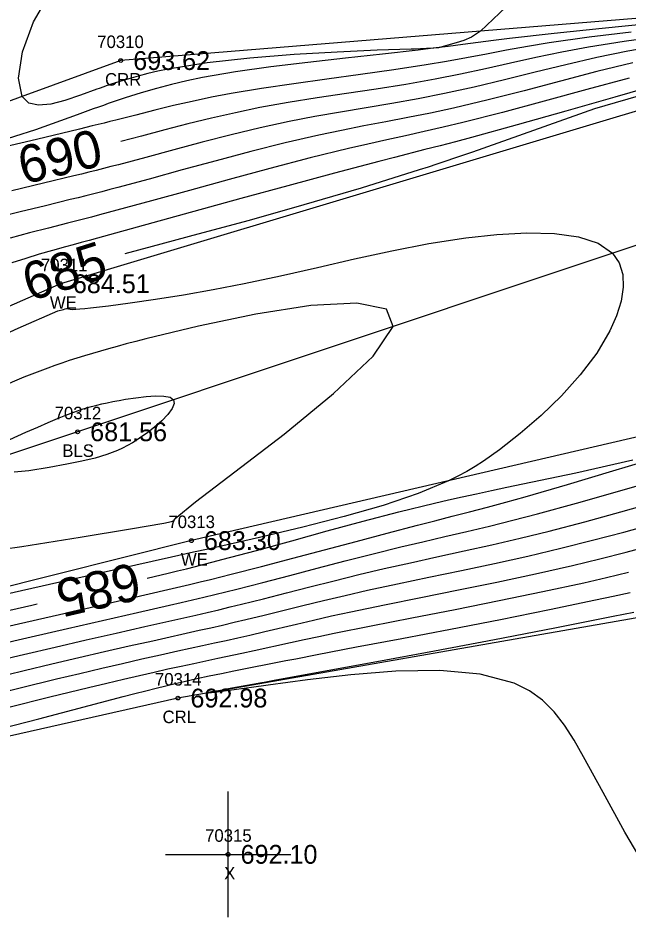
# Model space of a CAD drawing. Extents: x 1376587 to 1378239, y 1000335 to 1003031.
# Drawn here: x 1377106.6 to 1377155.3, y 1001513.1 to 1001584.8 of the extents above; entities that cross this region are included whole.
import ezdxf

# ---------------------------------------------------------------- set-up
doc = ezdxf.new("R2010")
doc.units = 0
for name, color, linetype in [('RD_DTM_BkLn1', 7, 'Continuous'), ('RD_DTM_BkLn_txCode', 7, 'Continuous'), ('RD_DTM_Major1', 7, 'Continuous'), ('RD_DTM_Major1_Lbl', 7, 'Continuous'), ('RD_DTM_Minor1', 7, 'Continuous'), ('RD_EX_H2O', 7, 'Continuous'), ('RD_EX_H2O_txCode', 7, 'Continuous'), ('RD_EX_Misc', 7, 'Continuous'), ('RD_EX_Misc_txCode', 7, 'Continuous'), ('RD_EX_TX_H2O_ELEV', 7, 'Continuous'), ('RD_EX_TX_Misc_ELEV', 7, 'Continuous'), ('RD_SMD_Locator', 7, 'Continuous')]:
    doc.layers.add(name, color=color, linetype=linetype)

msp = doc.modelspace()

# ---------------------------------------------------------------- linework, layer by layer
at = {"layer": 'RD_DTM_BkLn1'}
msp.add_lwpolyline([(1377322.969, 1001642.525), (1377293.605, 1001607.098), (1377249.432, 1001558.553), (1377170.427, 1001571.461), (1377111.377, 1001551.766), (1377054.733, 1001532.92), (1377033.73, 1001527.24), (1376971.435, 1001536.185), (1376926.988, 1001576.278)], dxfattribs=at)
at = {"layer": 'RD_DTM_Major1'}
for points in [[(1377157.881, 1001583.305), (1377154.99, 1001582.908), (1377152.156, 1001582.449), (1377150.02, 1001582.045), (1377147.949, 1001581.613), (1377145.922, 1001581.168), (1377143.919, 1001580.723), (1377141.921, 1001580.293), (1377139.909, 1001579.891), (1377137.566, 1001579.477), (1377135.2, 1001579.102), (1377132.831, 1001578.747), (1377130.482, 1001578.395), (1377128.174, 1001578.027), (1377125.928, 1001577.626), (1377123.968, 1001577.224), (1377122.059, 1001576.788), (1377120.184, 1001576.327), (1377118.325, 1001575.848), (1377116.466, 1001575.36), (1377114.833, 1001574.934)], [(1377156.946, 1001578.77), (1377152.642, 1001577.526), (1377147.765, 1001575.8), (1377142.89, 1001574.08), (1377142.173, 1001573.835), (1377141.461, 1001573.593), (1377140.752, 1001573.355), (1377140.046, 1001573.12), (1377139.341, 1001572.888), (1377138.635, 1001572.659), (1377134.009, 1001571.213), (1377129.443, 1001569.867), (1377125.058, 1001568.633), (1377120.977, 1001567.521), (1377117.32, 1001566.544), (1377115.147, 1001565.962)], [(1377116.914, 1001540.081), (1377118.593, 1001540.484), (1377119.334, 1001540.666), (1377120.061, 1001540.847), (1377120.776, 1001541.027), (1377121.485, 1001541.207), (1377122.19, 1001541.388), (1377122.896, 1001541.572), (1377125.66, 1001542.311), (1377128.466, 1001543.079), (1377131.302, 1001543.858), (1377134.154, 1001544.629), (1377137.01, 1001545.373), (1377139.858, 1001546.072), (1377140.964, 1001546.329), (1377142.08, 1001546.58), (1377143.22, 1001546.83), (1377144.396, 1001547.083), (1377145.623, 1001547.343), (1377146.913, 1001547.614), (1377151.134, 1001548.507), (1377155.692, 1001549.527)], [(1377103.735, 1001530.596), (1377106.791, 1001531.352), (1377109.684, 1001532.056), (1377111.544, 1001532.5), (1377113.297, 1001532.912), (1377114.95, 1001533.295), (1377116.51, 1001533.649), (1377117.985, 1001533.98), (1377119.381, 1001534.288), (1377121.341, 1001534.716), (1377122.288, 1001534.923), (1377123.229, 1001535.13), (1377124.172, 1001535.341), (1377125.13, 1001535.559), (1377126.312, 1001535.835), (1377128.833, 1001536.43), (1377130.197, 1001536.747), (1377131.645, 1001537.075), (1377133.192, 1001537.413), (1377135.87, 1001537.972), (1377138.755, 1001538.554), (1377141.772, 1001539.158), (1377144.847, 1001539.785), (1377147.907, 1001540.435), (1377150.878, 1001541.106), (1377153.057, 1001541.635), (1377155.168, 1001542.172), (1377157.238, 1001542.714)], [(1377077.245, 1001530.968), (1377081.358, 1001531.909), (1377085.388, 1001532.835), (1377089.149, 1001533.702), (1377090.474, 1001534.009), (1377091.751, 1001534.304), (1377093.001, 1001534.594), (1377094.242, 1001534.88), (1377095.493, 1001535.168), (1377096.773, 1001535.461), (1377100.254, 1001536.252), (1377103.943, 1001537.085), (1377107.732, 1001537.944), (1377108.148, 1001538.039)]]:
    msp.add_lwpolyline(points, dxfattribs=at)
at = {"layer": 'RD_DTM_Minor1'}
for points in [[(1377146.071, 1001586.122), (1377143.533, 1001583.723), (1377142.824, 1001583.234), (1377142.198, 1001582.984), (1377141.581, 1001582.805), (1377140.179, 1001582.401), (1377139.448, 1001582.342), (1377139.223, 1001582.332), (1377138.991, 1001582.323), (1377138.753, 1001582.314), (1377138.256, 1001582.299), (1377137.996, 1001582.291), (1377135.281, 1001582.201), (1377132.102, 1001582.062), (1377128.653, 1001581.858), (1377125.125, 1001581.573), (1377121.714, 1001581.19), (1377118.611, 1001580.694), (1377117.772, 1001580.522), (1377116.972, 1001580.338), (1377116.205, 1001580.142), (1377115.465, 1001579.936), (1377114.745, 1001579.718), (1377114.041, 1001579.489), (1377113.85, 1001579.424), (1377113.659, 1001579.358), (1377113.468, 1001579.291), (1377113.089, 1001579.157), (1377112.9, 1001579.089), (1377111.598, 1001578.617), (1377110.36, 1001578.2), (1377109.231, 1001577.909), (1377108.255, 1001577.817), (1377107.478, 1001577.995), (1377106.944, 1001578.514), (1377106.664, 1001579.987), (1377106.982, 1001582.073), (1377107.854, 1001584.463), (1377109.236, 1001586.852)], [(1377157.167, 1001584.344), (1377153.234, 1001583.948), (1377149.405, 1001583.546), (1377145.85, 1001583.14), (1377144.566, 1001582.98), (1377143.332, 1001582.822), (1377142.132, 1001582.665), (1377140.949, 1001582.509), (1377139.764, 1001582.357), (1377138.561, 1001582.208), (1377135.706, 1001581.88), (1377132.744, 1001581.559), (1377129.751, 1001581.229), (1377126.803, 1001580.873), (1377123.977, 1001580.478), (1377121.348, 1001580.027), (1377120.093, 1001579.768), (1377118.879, 1001579.483), (1377117.676, 1001579.165), (1377116.452, 1001578.807), (1377115.178, 1001578.403), (1377113.821, 1001577.945), (1377113.429, 1001577.809), (1377113.028, 1001577.668), (1377112.619, 1001577.523), (1377112.199, 1001577.373), (1377111.769, 1001577.219), (1377111.329, 1001577.06), (1377108.007, 1001575.865), (1377104.642, 1001574.792)], [(1377155.556, 1001583.646), (1377152.2, 1001583.235), (1377149.019, 1001582.782), (1377147.277, 1001582.497), (1377145.612, 1001582.202), (1377143.997, 1001581.902), (1377142.406, 1001581.603), (1377140.81, 1001581.31), (1377139.182, 1001581.029), (1377136.607, 1001580.63), (1377133.95, 1001580.257), (1377131.269, 1001579.897), (1377128.62, 1001579.536), (1377126.059, 1001579.161), (1377123.642, 1001578.759), (1377122.05, 1001578.453), (1377120.524, 1001578.128), (1377119.03, 1001577.783), (1377117.536, 1001577.418), (1377116.008, 1001577.033), (1377114.412, 1001576.63), (1377113.958, 1001576.515), (1377113.494, 1001576.399), (1377113.021, 1001576.282), (1377112.537, 1001576.162), (1377112.041, 1001576.04), (1377111.533, 1001575.915), (1377108.084, 1001575.087), (1377104.31, 1001574.194)], [(1377157.754, 1001582.569), (1377155.301, 1001582.131), (1377152.824, 1001581.614), (1377150.351, 1001581.044), (1377147.89, 1001580.445), (1377145.448, 1001579.845), (1377143.031, 1001579.269), (1377140.646, 1001578.745), (1377138.542, 1001578.333), (1377136.462, 1001577.964), (1377134.401, 1001577.618), (1377132.352, 1001577.275), (1377130.308, 1001576.917), (1377128.264, 1001576.523), (1377125.941, 1001576.017), (1377123.621, 1001575.459), (1377121.317, 1001574.867), (1377119.042, 1001574.26), (1377116.807, 1001573.655), (1377114.626, 1001573.073), (1377114.036, 1001572.919), (1377113.45, 1001572.767), (1377112.863, 1001572.617), (1377112.275, 1001572.468), (1377111.682, 1001572.32), (1377111.082, 1001572.173), (1377108.655, 1001571.59), (1377106.124, 1001570.992)], [(1377155.683, 1001581.205), (1377152.826, 1001580.498), (1377149.916, 1001579.742), (1377147.005, 1001578.978), (1377144.145, 1001578.248), (1377141.388, 1001577.592), (1377139.536, 1001577.194), (1377137.737, 1001576.835), (1377135.97, 1001576.497), (1377134.21, 1001576.163), (1377132.436, 1001575.815), (1377130.625, 1001575.435), (1377127.946, 1001574.816), (1377125.198, 1001574.125), (1377122.435, 1001573.394), (1377119.71, 1001572.653), (1377117.078, 1001571.931), (1377114.59, 1001571.259), (1377113.938, 1001571.087), (1377113.297, 1001570.92), (1377112.665, 1001570.757), (1377112.039, 1001570.597), (1377111.415, 1001570.441), (1377110.789, 1001570.285), (1377108.809, 1001569.803), (1377106.788, 1001569.313), (1377104.731, 1001568.797)], [(1377155.386, 1001579.987), (1377152.026, 1001579.073), (1377148.623, 1001578.138), (1377145.287, 1001577.238), (1377142.129, 1001576.433), (1377140.549, 1001576.057), (1377139.026, 1001575.711), (1377137.534, 1001575.382), (1377136.048, 1001575.056), (1377134.542, 1001574.721), (1377132.99, 1001574.363), (1377129.931, 1001573.611), (1377126.727, 1001572.776), (1377123.481, 1001571.899), (1377120.295, 1001571.023), (1377117.271, 1001570.188), (1377114.51, 1001569.435), (1377113.81, 1001569.248), (1377113.133, 1001569.069), (1377112.475, 1001568.896), (1377111.832, 1001568.729), (1377111.2, 1001568.566), (1377110.573, 1001568.407), (1377109.059, 1001568.022), (1377107.538, 1001567.629), (1377105.992, 1001567.212)], [(1377158.039, 1001579.541), (1377154.253, 1001578.471), (1377150.339, 1001577.349), (1377146.465, 1001576.249), (1377142.8, 1001575.24), (1377141.536, 1001574.905), (1377140.307, 1001574.586), (1377139.098, 1001574.276), (1377136.673, 1001573.658), (1377135.426, 1001573.337), (1377131.879, 1001572.404), (1377128.157, 1001571.399), (1377124.403, 1001570.37), (1377117.377, 1001568.426), (1377114.394, 1001567.606), (1377112.965, 1001567.217), (1377112.298, 1001567.036), (1377111.655, 1001566.862), (1377111.031, 1001566.692), (1377110.42, 1001566.525), (1377109.363, 1001566.231), (1377108.307, 1001565.927), (1377107.23, 1001565.601), (1377106.112, 1001565.241)], [(1377110.238, 1001561.521), (1377110.391, 1001561.571), (1377110.491, 1001561.596), (1377110.554, 1001561.602), (1377110.593, 1001561.595), (1377110.652, 1001561.564), (1377110.771, 1001561.541), (1377110.963, 1001561.536), (1377111.226, 1001561.548), (1377111.556, 1001561.573), (1377111.949, 1001561.611), (1377112.401, 1001561.659), (1377113.829, 1001561.827), (1377115.579, 1001562.054), (1377117.594, 1001562.343), (1377119.82, 1001562.694), (1377122.2, 1001563.109), (1377124.678, 1001563.588), (1377127.578, 1001564.211), (1377130.518, 1001564.882), (1377133.481, 1001565.559), (1377136.451, 1001566.204), (1377139.412, 1001566.776), (1377142.347, 1001567.236), (1377144.847, 1001567.513), (1377147.236, 1001567.641), (1377149.433, 1001567.588), (1377151.359, 1001567.321), (1377152.934, 1001566.806), (1377154.079, 1001566.008), (1377154.606, 1001565.235), (1377154.881, 1001564.321), (1377154.923, 1001563.294), (1377154.754, 1001562.183), (1377154.394, 1001561.016), (1377153.863, 1001559.821), (1377152.809, 1001558.052), (1377151.496, 1001556.315), (1377149.994, 1001554.643), (1377148.374, 1001553.068), (1377146.706, 1001551.622), (1377145.06, 1001550.338), (1377144.408, 1001549.867), (1377143.76, 1001549.425), (1377143.105, 1001549.007), (1377142.433, 1001548.61), (1377141.731, 1001548.23), (1377140.988, 1001547.863), (1377138.552, 1001546.847), (1377135.753, 1001545.898), (1377132.662, 1001545.004), (1377129.353, 1001544.154), (1377125.899, 1001543.337), (1377122.37, 1001542.542), (1377121.791, 1001542.413), (1377120.63, 1001542.155), (1377118.867, 1001541.765), (1377114.47, 1001540.786), (1377109.96, 1001539.775), (1377105.476, 1001538.762)], [(1377118.868, 1001544.604), (1377118.96, 1001544.637), (1377119.013, 1001544.666), (1377119.045, 1001544.697), (1377119.104, 1001544.789), (1377119.161, 1001544.862), (1377120.771, 1001546.184), (1377123.933, 1001548.569), (1377127.87, 1001551.588), (1377131.805, 1001554.812), (1377134.96, 1001557.814), (1377136.557, 1001560.164), (1377136.021, 1001561.55), (1377133.648, 1001562.039), (1377129.989, 1001561.838), (1377125.596, 1001561.157), (1377121.021, 1001560.202), (1377116.813, 1001559.182), (1377116.015, 1001558.976), (1377115.257, 1001558.775), (1377114.534, 1001558.58), (1377113.846, 1001558.389), (1377113.189, 1001558.202), (1377112.561, 1001558.019), (1377111.919, 1001557.827), (1377111.302, 1001557.636), (1377110.705, 1001557.445), (1377110.123, 1001557.252), (1377109.552, 1001557.056), (1377108.986, 1001556.855), (1377107.07, 1001556.121), (1377105.147, 1001555.308)], [(1377078.121, 1001546.544), (1377079.235, 1001547.086), (1377080.408, 1001547.672), (1377081.775, 1001548.356), (1377083.468, 1001549.197), (1377085.621, 1001550.252), (1377088.367, 1001551.576), (1377091.634, 1001553.138), (1377096.482, 1001555.399), (1377101.84, 1001557.863), (1377106.633, 1001560.036), (1377109.79, 1001561.42), (1377110.238, 1001561.521)], [(1377105.971, 1001551.161), (1377107.251, 1001551.732), (1377108.189, 1001552.146), (1377109.02, 1001552.508), (1377109.764, 1001552.824), (1377110.44, 1001553.097), (1377111.069, 1001553.335), (1377111.67, 1001553.541), (1377112.077, 1001553.668), (1377112.484, 1001553.784), (1377112.895, 1001553.891), (1377113.313, 1001553.992), (1377113.743, 1001554.086), (1377114.188, 1001554.177), (1377114.513, 1001554.239), (1377114.68, 1001554.27), (1377115.191, 1001554.359), (1377116.018, 1001554.486), (1377116.837, 1001554.584), (1377117.599, 1001554.634), (1377118.252, 1001554.619), (1377118.748, 1001554.52), (1377119.035, 1001554.32), (1377119.079, 1001554.013), (1377118.91, 1001553.615), (1377118.565, 1001553.152), (1377118.084, 1001552.652), (1377117.505, 1001552.139), (1377116.868, 1001551.641), (1377116.504, 1001551.38), (1377116.132, 1001551.133), (1377115.752, 1001550.898), (1377115.362, 1001550.678), (1377114.961, 1001550.472), (1377114.547, 1001550.282), (1377113.704, 1001549.956), (1377112.773, 1001549.673), (1377111.721, 1001549.417), (1377110.511, 1001549.173), (1377109.109, 1001548.924), (1377107.479, 1001548.656), (1377106.308, 1001548.535)], [(1377105.732, 1001536.249), (1377112.384, 1001537.764), (1377115.587, 1001538.498), (1377118.586, 1001539.193), (1377120.308, 1001539.599), (1377121.143, 1001539.798), (1377121.97, 1001539.998), (1377122.795, 1001540.2), (1377123.624, 1001540.406), (1377126.064, 1001541.028), (1377128.563, 1001541.682), (1377131.088, 1001542.353), (1377133.606, 1001543.026), (1377136.084, 1001543.686), (1377138.49, 1001544.316), (1377139.886, 1001544.675), (1377141.267, 1001545.028), (1377142.656, 1001545.385), (1377144.076, 1001545.758), (1377145.549, 1001546.154), (1377147.099, 1001546.586), (1377150.464, 1001547.569), (1377154.093, 1001548.659), (1377157.855, 1001549.783)], [(1377104.761, 1001534.757), (1377107.656, 1001535.425), (1377110.56, 1001536.089), (1377116.144, 1001537.36), (1377118.699, 1001537.945), (1377119.636, 1001538.161), (1377120.545, 1001538.373), (1377121.436, 1001538.582), (1377122.317, 1001538.793), (1377123.196, 1001539.006), (1377124.084, 1001539.225), (1377126.163, 1001539.752), (1377128.309, 1001540.309), (1377130.503, 1001540.884), (1377132.726, 1001541.463), (1377134.956, 1001542.034), (1377137.174, 1001542.583), (1377138.922, 1001542.999), (1377140.671, 1001543.406), (1377142.44, 1001543.818), (1377144.25, 1001544.248), (1377146.122, 1001544.708), (1377148.076, 1001545.212), (1377151.196, 1001546.068), (1377154.464, 1001547.005), (1377157.795, 1001547.973)], [(1377104.521, 1001533.415), (1377107.059, 1001534.014), (1377109.583, 1001534.6), (1377112.062, 1001535.169), (1377114.46, 1001535.714), (1377116.747, 1001536.232), (1377119.861, 1001536.936), (1377120.802, 1001537.151), (1377121.723, 1001537.363), (1377122.634, 1001537.576), (1377123.545, 1001537.793), (1377124.467, 1001538.017), (1377126.219, 1001538.454), (1377128.036, 1001538.918), (1377129.914, 1001539.398), (1377131.846, 1001539.887), (1377133.827, 1001540.376), (1377135.851, 1001540.856), (1377137.932, 1001541.326), (1377140.054, 1001541.79), (1377142.221, 1001542.261), (1377144.435, 1001542.752), (1377146.7, 1001543.274), (1377149.02, 1001543.842), (1377151.856, 1001544.586), (1377154.74, 1001545.383), (1377160.509, 1001547.011)], [(1377102.35, 1001541.974), (1377106.929, 1001542.624), (1377111.583, 1001543.352), (1377115.599, 1001544.017), (1377118.265, 1001544.481), (1377118.868, 1001544.604)], [(1377104.471, 1001532.097), (1377107.107, 1001532.735), (1377109.327, 1001533.263), (1377111.471, 1001533.764), (1377113.532, 1001534.239), (1377115.5, 1001534.686), (1377117.366, 1001535.106), (1377121.069, 1001535.932), (1377122.007, 1001536.143), (1377122.936, 1001536.355), (1377123.865, 1001536.57), (1377124.808, 1001536.793), (1377126.262, 1001537.147), (1377129.351, 1001537.911), (1377130.997, 1001538.313), (1377132.718, 1001538.721), (1377134.521, 1001539.132), (1377136.914, 1001539.65), (1377139.417, 1001540.173), (1377142.002, 1001540.709), (1377144.639, 1001541.266), (1377147.3, 1001541.852), (1377149.955, 1001542.475), (1377152.477, 1001543.111), (1377154.971, 1001543.775), (1377157.443, 1001544.451)], [(1377105.775, 1001529.786), (1377109.164, 1001530.626), (1377112.253, 1001531.378), (1377113.703, 1001531.725), (1377115.048, 1001532.042), (1377116.301, 1001532.333), (1377117.476, 1001532.6), (1377118.586, 1001532.848), (1377119.644, 1001533.08), (1377120.642, 1001533.295), (1377122.571, 1001533.703), (1377124.487, 1001534.109), (1377125.468, 1001534.321), (1377128.378, 1001534.96), (1377129.459, 1001535.195), (1377130.616, 1001535.442), (1377131.863, 1001535.702), (1377134.795, 1001536.291), (1377138.051, 1001536.929), (1377141.505, 1001537.604), (1377145.03, 1001538.303), (1377148.498, 1001539.017), (1377151.782, 1001539.732), (1377153.595, 1001540.151), (1377155.332, 1001540.568)], [(1377104.327, 1001527.868), (1377108.276, 1001528.879), (1377115.007, 1001530.648), (1377115.948, 1001530.891), (1377116.825, 1001531.114), (1377117.647, 1001531.319), (1377118.423, 1001531.509), (1377119.162, 1001531.685), (1377119.873, 1001531.85), (1377120.889, 1001532.077), (1377121.88, 1001532.289), (1377122.86, 1001532.492), (1377123.847, 1001532.691), (1377128.006, 1001533.517), (1377128.782, 1001533.67), (1377130.488, 1001534.003), (1377133.643, 1001534.607), (1377137.251, 1001535.292), (1377141.137, 1001536.033), (1377145.125, 1001536.807), (1377149.04, 1001537.588), (1377152.707, 1001538.352), (1377154.118, 1001538.659), (1377155.479, 1001538.961)], [(1377157.026, 1001516.505), (1377155.046, 1001519.834), (1377153.313, 1001522.995), (1377151.763, 1001525.848), (1377150.998, 1001527.173), (1377150.225, 1001528.37), (1377149.403, 1001529.43), (1377148.49, 1001530.348), (1377147.445, 1001531.117), (1377146.228, 1001531.729), (1377143.506, 1001532.445), (1377140.284, 1001532.725), (1377136.772, 1001532.671), (1377133.18, 1001532.389), (1377129.717, 1001531.982), (1377126.594, 1001531.556), (1377125.247, 1001531.369), (1377124.064, 1001531.208), (1377123.077, 1001531.077), (1377122.316, 1001530.981), (1377121.812, 1001530.925), (1377121.598, 1001530.914), (1377121.698, 1001530.954), (1377122.1, 1001531.04), (1377122.77, 1001531.17), (1377123.676, 1001531.339), (1377126.065, 1001531.774), (1377126.26, 1001531.809), (1377127.066, 1001531.955), (1377131.001, 1001532.671), (1377135.254, 1001533.452), (1377139.863, 1001534.308), (1377144.658, 1001535.211), (1377149.468, 1001536.135), (1377154.124, 1001537.051), (1377155.766, 1001537.382)]]:
    msp.add_lwpolyline(points, dxfattribs=at)
at = {"layer": 'RD_EX_H2O'}
for points in [[(1377371.252, 1001717.109), (1377370.663, 1001706.746), (1377369.728, 1001695.357), (1377362.942, 1001684.236), (1377342.423, 1001669.398), (1377312.741, 1001659.466), (1377279.928, 1001621.341), (1377233.434, 1001598.677), (1377169.941, 1001585.879), (1377114.813, 1001581.379), (1377057.35, 1001560.459), (1377030.227, 1001561.127), (1376975.162, 1001566.792), (1376927.948, 1001589.938)], [(1377396.047, 1001693.167), (1377388.971, 1001691.891), (1377383.547, 1001681.612), (1377370.954, 1001666.151), (1377345.792, 1001650.036), (1377349.116, 1001628.131), (1377334.126, 1001625.317), (1377311.323, 1001589.505), (1377259.373, 1001541.156), (1377186.141, 1001542.199), (1377119.382, 1001530.527), (1377065.136, 1001518.284), (1377035.175, 1001514.747), (1376967.402, 1001521.021), (1376926.832, 1001536.774)], [(1377334.456, 1001660.576), (1377318.223, 1001649.936), (1377286.502, 1001611.675), (1377286.502, 1001611.675), (1377237.873, 1001575.182), (1377169.705, 1001581.472), (1377109.998, 1001563.579), (1377053.341, 1001538.726), (1377032.875, 1001532.424), (1376974.355, 1001543.191), (1376926.217, 1001584.14)], [(1377346.874, 1001651.39), (1377329.206, 1001632.325), (1377301.199, 1001598.995), (1377255.164, 1001549.418), (1377172.114, 1001555.099), (1377120.453, 1001543.089), (1377120.453, 1001543.089), (1377055.21, 1001526.728), (1377035.209, 1001521.298), (1376967.617, 1001528.254), (1376929.582, 1001558.001)]]:
    msp.add_lwpolyline(points, dxfattribs=at)
at = {"layer": 'RD_EX_Misc'}
for p, q in [((1377123.382, 1001513.063), (1377123.382, 1001523.063)), ((1377118.382, 1001518.063), (1377128.382, 1001518.063))]:
    msp.add_line(p, q, dxfattribs=at)
at = {"layer": 'RD_SMD_Locator'}
for centre in [(1377114.813, 1001581.379), (1377109.998, 1001563.579), (1377111.377, 1001551.766), (1377120.453, 1001543.089), (1377119.382, 1001530.527), (1377123.382, 1001518.063)]:
    msp.add_circle(centre, 0.15, dxfattribs=at)

# ---------------------------------------------------------------- texts
at = {"layer": 'RD_DTM_BkLn_txCode'}
for s, p in [('70312', (1377109.542, 1001552.766)), ('BLS', (1377110.149, 1001549.766))]:
    msp.add_text(s, height=1, dxfattribs=at).set_placement(p)
at = {"layer": 'RD_DTM_Major1_Lbl'}
for s, rotation, p in [('690', 13.54181, (1377107.05, 1001571.487)), ('685', 17.37461, (1377107.565, 1001562.161)), ('685', 193.11219, (1377115.967, 1001541.387))]:
    msp.add_text(s, height=3, rotation=rotation, dxfattribs=at).set_placement(p)
at = {"layer": 'RD_EX_H2O_txCode'}
for s, p in [('70310', (1377112.939, 1001582.379)), ('CRR', (1377113.561, 1001579.379)), ('70311', (1377108.447, 1001564.579)), ('WE', (1377109.159, 1001561.579)), ('70313', (1377118.618, 1001544.089)), ('WE', (1377119.614, 1001541.089)), ('70314', (1377117.547, 1001531.527)), ('CRL', (1377118.154, 1001528.527))]:
    msp.add_text(s, height=1, dxfattribs=at).set_placement(p)
at = {"layer": 'RD_EX_Misc_txCode'}
for s, p in [('70315', (1377121.547, 1001519.063)), ('X', (1377123.067, 1001516.063))]:
    msp.add_text(s, height=1, dxfattribs=at).set_placement(p)
at = {"layer": 'RD_EX_TX_H2O_ELEV'}
for s, p in [('693.62', (1377115.813, 1001580.629)), ('684.51', (1377110.998, 1001562.829)), ('683.30', (1377121.453, 1001542.339)), ('692.98', (1377120.382, 1001529.777))]:
    msp.add_text(s, height=1.5, dxfattribs=at).set_placement(p)
at = {"layer": 'RD_EX_TX_Misc_ELEV'}
for s, p in [('681.56', (1377112.377, 1001551.016)), ('692.10', (1377124.382, 1001517.313))]:
    msp.add_text(s, height=1.5, dxfattribs=at).set_placement(p)

doc.saveas('drawing.dxf')
